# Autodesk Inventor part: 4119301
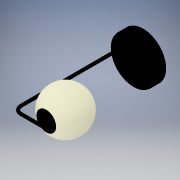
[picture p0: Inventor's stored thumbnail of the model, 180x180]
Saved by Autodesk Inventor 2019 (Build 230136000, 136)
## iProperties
Created: 2020-11
Part Number: 4119301
Material: Generic
Document SubType Name: Modeling
Designer: user
Density: 1 g/cm^3
Appearance: Default
Author: user
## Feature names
1. Extrusion1
2. Sweep1
3. Extrusion3
4. Revolution1
5. Fillet1
## Parameters: d1 = 35 mm, d2 = 0, d3 = -35 mm, d14 = 355 mm, d17 = 25 mm, d18 = 0, d19 = 0, d28 = 3 mm, d29 = 8 mm, d30 = 0, d31 = 0, d32 = 15 mm, d34 = 185 mm, d35 = 90 deg, d38 = 4 mm
